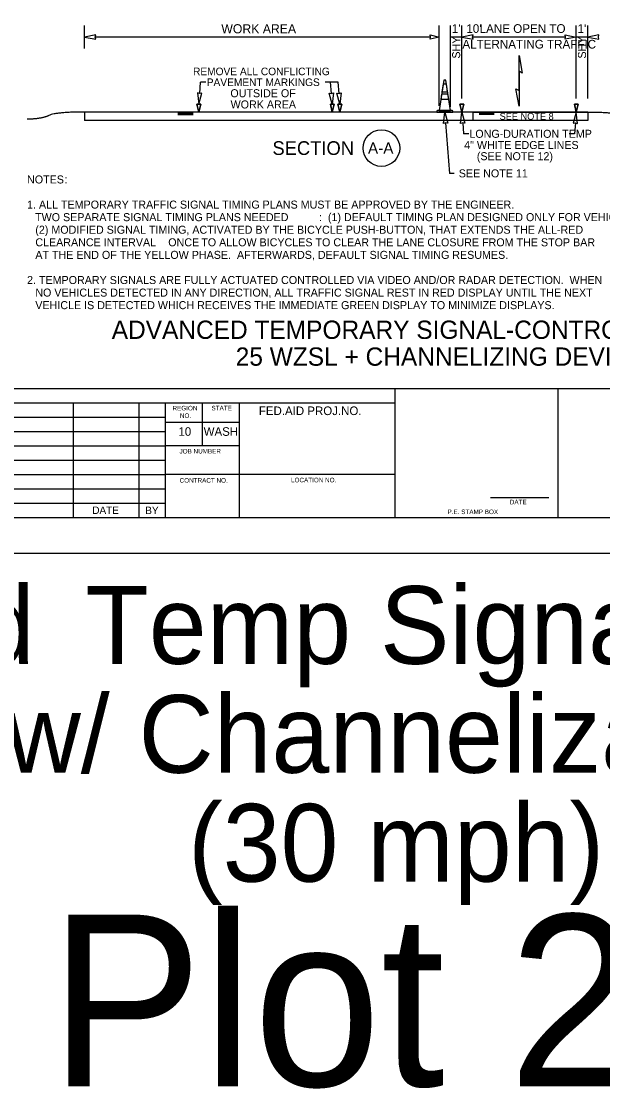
# Model space of a CAD drawing. Extents: x 99982 to 100176, y 99905 to 100011.
# Drawn here: x 100044.19 to 100049.27, y 99935.01 to 99944.34 of the extents above; entities that cross this region are included whole.
import ezdxf

# ---------------------------------------------------------------- set-up
doc = ezdxf.new("R2010")
doc.units = 0
for name, color, linetype in [('SH_DE_DetailHeading1Text', 7, 'Continuous'), ('SH_GI_GeneralNotesBodyText', 7, 'Continuous'), ('SH_GI_PlotLimits', 7, 'Continuous'), ('SH_GI_SheetBorder', 7, 'Continuous'), ('SH_GI_SheetLocationText', 7, 'Continuous'), ('SH_GI_SheetTextInCells', 7, 'Continuous'), ('TR_WZ_TrafficConeElev', 7, 'Continuous'), ('TR_WZ_WorkZoneDetails', 7, 'Continuous'), ('TR_WZ_WorkZoneTextCurrent', 7, 'Continuous')]:
    doc.layers.add(name, color=color, linetype=linetype)

msp = doc.modelspace()

# ---------------------------------------------------------------- linework, layer by layer
at = {"layer": 'SH_GI_PlotLimits'}
msp.add_lwpolyline([(100039.0625, 99939.6875), (100056.0625, 99939.6875), (100056.0625, 99950.6875), (100039.0625, 99950.6875)], close=True, dxfattribs=at)
at = {"layer": 'SH_GI_SheetBorder'}
for p, q in [((100040, 99941.1259), (100055.75, 99941.1259)), ((100047.4566, 99940), (100047.4566, 99941.1259)), ((100048.8828, 99940), (100048.8828, 99941.1259)), ((100040, 99941.0008), (100047.4566, 99941.0008)), ((100044.641, 99941.0008), (100044.641, 99940)), ((100045.2164, 99941.0008), (100045.2164, 99940)), ((100045.4451, 99941.0008), (100045.4451, 99940)), ((100045.7719, 99940.6255), (100045.7719, 99941.0008)), ((100046.0956, 99940), (100046.0956, 99941.0008)), ((100042.1821, 99940.8757), (100045.4466, 99940.8757)), ((100046.0958, 99940.831), (100045.4466, 99940.831)), ((100042.1821, 99940.7506), (100045.4466, 99940.7506)), ((100040, 99940.6255), (100045.4466, 99940.6255)), ((100046.0958, 99940.6255), (100045.4466, 99940.6255)), ((100040, 99940.5004), (100045.4466, 99940.5004)), ((100040, 99940.3753), (100045.4466, 99940.3753)), ((100047.4566, 99940.3753), (100045.4466, 99940.3753)), ((100040, 99940.2502), (100045.4466, 99940.2502)), ((100040, 99940.1251), (100045.4466, 99940.1251)), ((100048.2903, 99940.1733), (100048.802, 99940.1733)), ((100040, 99940), (100055.75, 99940))]:
    msp.add_line(p, q, dxfattribs=at)
at = {"layer": 'TR_WZ_TrafficConeElev'}
for p, q in [((100047.8754, 99943.7863), (100047.8655, 99943.7213)), ((100047.9057, 99943.7863), (100047.8754, 99943.7863)), ((100047.9156, 99943.7213), (100047.9057, 99943.7863)), ((100047.8624, 99943.7013), (100047.8555, 99943.6563)), ((100047.9187, 99943.7013), (100047.8624, 99943.7013)), ((100047.8655, 99943.7213), (100047.9156, 99943.7213)), ((100047.9256, 99943.6563), (100047.9187, 99943.7013)), ((100047.8555, 99943.6563), (100047.9256, 99943.6563)), ((100047.8262, 99943.5588), (100047.8212, 99943.5538)), ((100047.8212, 99943.5538), (100047.8212, 99943.5438)), ((100047.8212, 99943.5438), (100047.9599, 99943.5438)), ((100047.8405, 99943.5588), (100047.8262, 99943.5588)), ((100047.9599, 99943.5538), (100047.9549, 99943.5588)), ((100047.9599, 99943.5438), (100047.9599, 99943.5538))]:
    msp.add_line(p, q, dxfattribs=at)
msp.add_lwpolyline([(100047.8405, 99943.5588), (100047.9405, 99943.5588), (100047.8999, 99943.8238), (100047.8812, 99943.8238)], close=True, dxfattribs=at)
msp.add_lwpolyline([(100047.8405, 99943.5588), (100047.9405, 99943.5588), (100047.8999, 99943.8238), (100047.8812, 99943.8238)], close=True, dxfattribs=at)
msp.add_lwpolyline([(100047.9549, 99943.5588), (100047.9405, 99943.5588), (100047.8405, 99943.5588)], dxfattribs=at)
at = {"layer": 'TR_WZ_WorkZoneDetails'}
for p, q in [((100044.7405, 99944.0999), (100044.7405, 99944.2999)), ((100047.8405, 99943.5988), (100047.8405, 99944.2999)), ((100047.9405, 99943.5888), (100047.9405, 99944.2999)), ((100048.0405, 99943.6636), (100048.0405, 99944.2999)), ((100049.0405, 99943.6636), (100049.0405, 99944.2999)), ((100049.1405, 99943.6636), (100049.1405, 99944.2999)), ((100047.7656, 99944.1999), (100044.8342, 99944.1999)), ((100048.0405, 99944.1999), (100047.9405, 99944.1999)), ((100048.9468, 99944.1999), (100048.1343, 99944.1999)), ((100049.1405, 99944.1999), (100049.0405, 99944.1999)), ((100048.5405, 99943.9003), (100048.5405, 99943.7315)), ((100048.5405, 99943.7315), (100048.5405, 99943.9003)), ((100045.7479, 99943.7071), (100045.7557, 99943.8046)), ((100045.8018, 99943.8046), (100045.7557, 99943.8046)), ((100046.9586, 99943.8046), (100046.8458, 99943.8046)), ((100046.8997, 99943.7071), (100046.8919, 99943.8046)), ((100046.9664, 99943.7071), (100046.9586, 99943.8046)), ((100044.7405, 99943.5438), (100044.7405, 99943.4688)), ((100049.1405, 99943.5438), (100044.7405, 99943.5438)), ((100045.5575, 99943.5386), (100045.6905, 99943.5386)), ((100045.5575, 99943.533), (100045.6905, 99943.533)), ((100045.5575, 99943.5273), (100045.6905, 99943.5273)), ((100045.5575, 99943.5221), (100045.6905, 99943.5221)), ((100048.3235, 99943.5382), (100048.1905, 99943.5382)), ((100048.3235, 99943.5326), (100048.1905, 99943.5326)), ((100048.3235, 99943.5269), (100048.1905, 99943.5269)), ((100048.3235, 99943.5217), (100048.1905, 99943.5217)), ((100049.1405, 99943.5438), (100049.1405, 99943.4688)), ((100049.1405, 99943.4688), (100044.7405, 99943.4688)), ((100047.898, 99943.4504), (100047.9333, 99943.0068)), ((100048.048, 99943.4504), (100048.0557, 99943.3528)), ((100049.0331, 99943.4504), (100049.0253, 99943.3528)), ((100048.1019, 99943.3528), (100048.0557, 99943.3528)), ((100049.0253, 99943.3528), (100048.9792, 99943.3528)), ((100047.9733, 99943.0068), (100047.9333, 99943.0068))]:
    msp.add_line(p, q, dxfattribs=at)
for points in [[(100044.7405, 99944.1999), (100044.8388, 99944.1806), (100044.8342, 99944.1999), (100044.8388, 99944.2192)], [(100047.8405, 99944.1999), (100047.7619, 99944.1806), (100047.7656, 99944.1999), (100047.7619, 99944.2192)], [(100048.0405, 99944.1999), (100048.1388, 99944.1806), (100048.1343, 99944.1999), (100048.1388, 99944.2192)], [(100049.0405, 99944.1999), (100048.9423, 99944.1806), (100048.9468, 99944.1999), (100048.9423, 99944.2192)], [(100049.1405, 99944.1999), (100049.2388, 99944.1806), (100049.2343, 99944.1999), (100049.2388, 99944.2192)], [(100048.5405, 99944.0379), (100048.5675, 99943.8847), (100048.5405, 99943.9003)], [(100045.7405, 99943.6136), (100045.7674, 99943.7101), (100045.7479, 99943.7071), (100045.729, 99943.7131)], [(100046.9071, 99943.6136), (100046.8802, 99943.7101), (100046.8998, 99943.7071), (100046.9186, 99943.7131)], [(100046.9738, 99943.6136), (100046.9469, 99943.7101), (100046.9665, 99943.7071), (100046.9853, 99943.7131)], [(100048.5405, 99943.5939), (100048.5135, 99943.7471), (100048.5405, 99943.7315)], [(100045.7405, 99943.5438), (100045.7238, 99943.6136), (100045.7572, 99943.6136)], [(100046.9072, 99943.5438), (100046.8905, 99943.6136), (100046.9238, 99943.6136)], [(100046.9739, 99943.5438), (100046.9572, 99943.6136), (100046.9905, 99943.6136)], [(100048.0405, 99943.5438), (100048.0238, 99943.6136), (100048.0572, 99943.6136)], [(100049.0405, 99943.5438), (100049.0238, 99943.6136), (100049.0572, 99943.6136)], [(100047.8905, 99943.5438), (100047.9175, 99943.4474), (100047.8979, 99943.4504), (100047.8791, 99943.4443)], [(100048.0405, 99943.5438), (100048.0675, 99943.4474), (100048.0479, 99943.4504), (100048.0291, 99943.4443)], [(100048.1405, 99943.5438), (100049.1405, 99943.5438), (100049.1405, 99943.4688), (100048.1405, 99943.4688)], [(100048.1405, 99943.5438), (100049.1405, 99943.5438), (100049.1405, 99943.4688), (100048.1405, 99943.4688)], [(100049.0405, 99943.5438), (100049.0136, 99943.4474), (100049.0331, 99943.4504), (100049.052, 99943.4443)]]:
    msp.add_lwpolyline(points, close=True, dxfattribs=at)
for points in [[(100045.7572, 99943.6136), (100045.7238, 99943.6136), (100045.7405, 99943.5438), (100045.7572, 99943.6136)], [(100046.9238, 99943.6136), (100046.8905, 99943.6136), (100046.9072, 99943.5438), (100046.9238, 99943.6136)], [(100046.9905, 99943.6136), (100046.9572, 99943.6136), (100046.9739, 99943.5438), (100046.9905, 99943.6136)], [(100048.0572, 99943.6136), (100048.0238, 99943.6136), (100048.0405, 99943.5438), (100048.0572, 99943.6136)], [(100049.0572, 99943.6136), (100049.0238, 99943.6136), (100049.0405, 99943.5438), (100049.0572, 99943.6136)]]:
    msp.add_lwpolyline(points, dxfattribs=at)
msp.add_circle((100047.3371, 99943.2289), 0.16, dxfattribs=at)
for points in [[(100044.7405, 99943.5438), (100044.4893, 99943.5438), (100044.3639, 99943.4817), (100044.2384, 99943.4817)], [(100049.1405, 99943.5438), (100049.3917, 99943.544), (100049.5172, 99943.4819), (100049.6427, 99943.482)]]:
    msp.add_open_spline(points, degree=2, dxfattribs=at)

# ---------------------------------------------------------------- texts
at = {"layer": 'SH_DE_DetailHeading1Text'}
for s, p in [('ADVANCED TEMPORARY SIGNAL-CONTROLLED ALTERNATING 1-LANE, 2-WAY TRAFFIC', (100044.9788, 99941.5606)), ('25 WZSL + CHANNELIZING DEVICES (30 MPH HIGHWAYS, 8+ DAYS)', (100046.0628, 99941.3259))]:
    msp.add_text(s, height=0.16, rotation=360, dxfattribs=at).set_placement(p)
at = {"layer": 'SH_GI_GeneralNotesBodyText'}
for s, p in [('NOTES', (100044.2384, 99942.9196)), (':', (100044.5659, 99942.9196)), ('1. ALL TEMPORARY TRAFFIC SIGNAL TIMING PLANS MUST BE APPROVED BY THE ENGINEER.', (100044.2384, 99942.6998)), ('TWO SEPARATE SIGNAL TIMING PLANS NEEDED', (100044.3084, 99942.5899)), (':  (1) DEFAULT TIMING PLAN DESIGNED ONLY FOR VEHICLES. ', (100046.7909, 99942.5899)), ('(2) MODIFIED SIGNAL TIMING, ACTIVATED BY THE BICYCLE PUSH-BUTTON, THAT EXTENDS THE ALL-RED ', (100044.3106, 99942.48)), ('CLEARANCE INTERVAL ', (100044.3106, 99942.3701)), ('ONCE', (100045.4729, 99942.3701)), (' TO ALLOW BICYCLES TO CLEAR THE LANE CLOSURE FROM THE STOP BAR ', (100045.7357, 99942.3701)), ('AT THE END OF THE YELLOW PHASE.  AFTERWARDS, DEFAULT SIGNAL TIMING RESUMES.', (100044.3106, 99942.2602)), ('2. TEMPORARY SIGNALS ARE FULLY ACTUATED CONTROLLED VIA VIDEO AND/OR RADAR DETECTION.  WHEN ', (100044.2384, 99942.0404)), ('NO VEHICLES DETECTED IN ANY DIRECTION, ALL TRAFFIC SIGNAL REST IN RED DISPLAY UNTIL THE NEXT ', (100044.3106, 99941.9305)), ('VEHICLE IS DETECTED WHICH RECEIVES THE IMMEDIATE GREEN DISPLAY TO MINIMIZE DISPLAYS.', (100044.3106, 99941.8206))]:
    msp.add_text(s, height=0.07, rotation=360, dxfattribs=at).set_placement(p)
at = {"layer": 'SH_GI_SheetLocationText'}
for s, height, p in [('Advanced', 0.68, (100040.2607, 99938.7191)), (' Temp Signal-Controlled', 0.68, (100044.4951, 99938.7191)), ('Alt Traffic w/ Channelization Devices', 0.68, (100039.9592, 99937.7671)), (' (30 mph)', 0.68, (100045.3937, 99936.8151)), ('Plot 23', 1.5, (100044.4341, 99935.0267))]:
    msp.add_text(s, height=height, dxfattribs=at).set_placement(p)
at = {"layer": 'SH_GI_SheetTextInCells'}
for s, height, p in [('REGION', 0.04003, (100045.5099, 99940.9352)), ('STATE', 0.04003, (100045.8511, 99940.9357)), ('FED.AID PROJ.NO.', 0.07506, (100046.2652, 99940.8945)), ('NO.', 0.04003, (100045.5752, 99940.869)), ('10', 0.07506, (100045.5621, 99940.7131)), ('WASH', 0.07506, (100045.7826, 99940.7131)), ('JOB NUMBER', 0.04003, (100045.5712, 99940.5587)), ('CONTRACT NO.', 0.040032, (100045.5725, 99940.3037)), ('LOCATION NO.', 0.040032, (100046.5465, 99940.3067)), ('DATE', 0.04003, (100048.4597, 99940.1141)), ('DATE', 0.06505, (100044.8091, 99940.03)), ('BY', 0.06505, (100045.2725, 99940.0285)), ('P.E. STAMP BOX', 0.040032, (100047.915, 99940.0286))]:
    msp.add_text(s, height=height, dxfattribs=at).set_placement(p)
at = {"layer": 'TR_WZ_WorkZoneDetails'}
for s, height, p in [('WORK AREA', 0.08, (100045.937, 99944.2319)), ("10'", 0.076, (100048.0794, 99944.2359)), (' LANE OPEN TO', 0.076, (100048.1674, 99944.2359)), ("1'", 0.076, (100047.9525, 99944.2359)), ("1'", 0.076, (100049.0522, 99944.2359)), ('ALTERNATING TRAFFIC', 0.076, (100048.0449, 99944.0991))]:
    msp.add_text(s, height=height, dxfattribs=at).set_placement(p)
for s, height, rotation, p in [('SHY', 0.07, 90, (100048.0255, 99944.0112)), ('SHY', 0.07, 90, (100049.1255, 99944.0112)), ('SECTION', 0.12, 360, (100046.384, 99943.1689)), ('A-A', 0.1, 360, (100047.2192, 99943.1789))]:
    msp.add_text(s, height=height, rotation=rotation, dxfattribs=at).set_placement(p)
at = {"layer": 'TR_WZ_WorkZoneTextCurrent'}
for s, height, p in [('REMOVE ALL CONFLICTING', 0.0665, (100045.6895, 99943.8659)), ('PAVEMENT MARKINGS', 0.0665, (100045.8095, 99943.7714)), ('OUTSIDE OF', 0.07, (100046.016, 99943.6734)), ('WORK AREA', 0.07, (100046.018, 99943.5754)), ('SEE NOTE 8', 0.06, (100048.3705, 99943.4763)), ('LONG-DURATION TEMP', 0.07, (100048.1059, 99943.3188)), ('4" WHITE EDGE LINES', 0.07, (100048.0607, 99943.2208)), ('(SEE NOTE 12)', 0.07, (100048.171, 99943.1228)), ('SEE NOTE 11', 0.07, (100048.0133, 99942.9728))]:
    msp.add_text(s, height=height, dxfattribs=at).set_placement(p)

doc.saveas('drawing.dxf')
